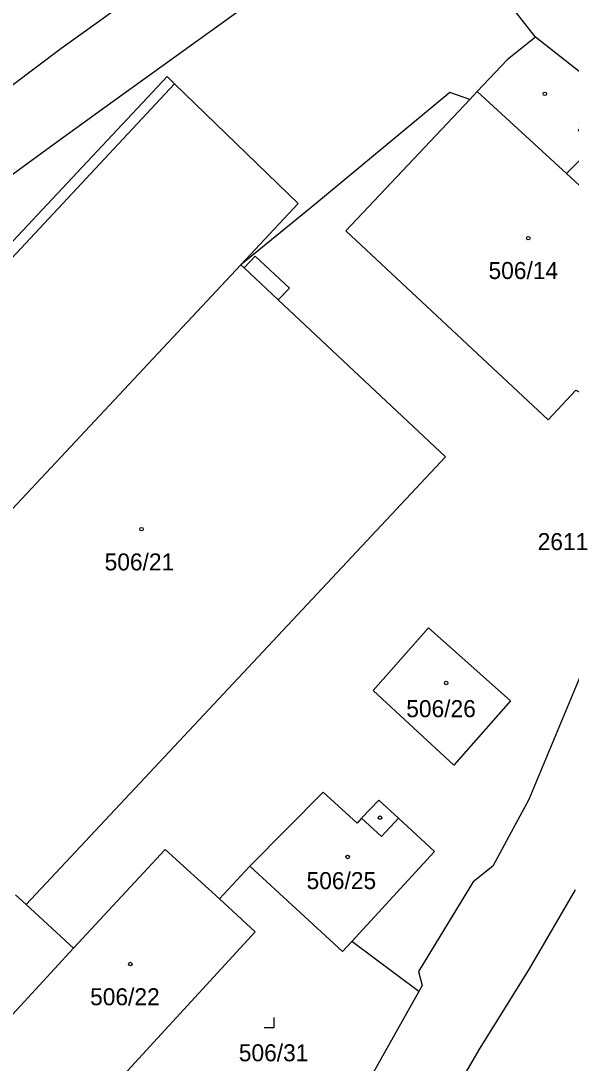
# Model space of a CAD drawing. Extents: x -679220 to -673243, y -1075091 to -1066557.
# Drawn here: x -677079.2 to -677024.2, y -1070793.9 to -1070689.7 of the extents above; entities that cross this region are included whole.
import ezdxf

# ---------------------------------------------------------------- set-up
doc = ezdxf.new("R2010")
doc.units = 0
for name, color, linetype in [('Hranice parcel', 7, 'Continuous'), ('Parcelní čísla', 7, 'Continuous'), ('Vnitřní kresba', 7, 'Continuous'), ('Značky budov', 7, 'Continuous'), ('Značky kultur', 7, 'Continuous')]:
    doc.layers.add(name, color=color, linetype=linetype)

msp = doc.modelspace()

# ---------------------------------------------------------------- linework, layer by layer
at = {"layer": 'Hranice parcel'}
for p, q in [((-677020.51, -1070697.05), (-677027.74, -1070691.36)), ((-677099.09, -1070758.91), (-677057.18, -1070714.13)), ((-677056.28, -1070774.23), (-677059.31, -1070777.52)), ((-677078.63, -1070778.07), (-677079.67, -1070777.1)), ((-677078.63, -1070778.07), (-677073.89, -1070782.45)), ((-677039.39, -1070786.77), (-677046.09, -1070781.76)), ((-677083.16, -1070792.51), (-677073.89, -1070782.45))]:
    msp.add_line(p, q, dxfattribs=at)
for points in [[(-677135.39, -1070729.77), (-677126.91, -1070726.13), (-677119.11, -1070722.08), (-677111.25, -1070717.42), (-677103.91, -1070713.3), (-677097.19, -1070709.11), (-677075.17, -1070692.52), (-677062.55, -1070683.44), (-677056.34, -1070679.02), (-677044.15, -1070670.16), (-677029.88, -1070660.86), (-677019.47, -1070653.76)], [(-677003.15, -1070655.19), (-677007.73, -1070657.23), (-677013.21, -1070659.83), (-677015.86, -1070661.26), (-677019.09, -1070662.86), (-677021.15, -1070664.15), (-677023.81, -1070665.65), (-677026.34, -1070667.21), (-677028.95, -1070668.79), (-677031.47, -1070670.4), (-677034.01, -1070671.98), (-677036.54, -1070673.73), (-677039.05, -1070675.44), (-677041.45, -1070677.28), (-677070.75, -1070698.39), (-677076.54, -1070702.6), (-677081.33, -1070706.06), (-677093, -1070715.15), (-677095.02, -1070716.41)], [(-677027.74, -1070691.36), (-677030.83, -1070687.38), (-676997.65, -1070663.02)], [(-677027.74, -1070691.36), (-677030.57, -1070693.65), (-677033.54, -1070696.8), (-677034.28, -1070697.59)], [(-677090.97, -1070723.48), (-677064.53, -1070695.31), (-677063.8, -1070696.05), (-677051.44, -1070708.01), (-677057.18, -1070714.13)], [(-677034.28, -1070697.59), (-677036.28, -1070696.89), (-677049.79, -1070708.11), (-677057.18, -1070714.13)], [(-677034.28, -1070697.59), (-677046.67, -1070710.74), (-677026.45, -1070729.62), (-677023.7, -1070726.67), (-677004.38, -1070736.72), (-676997.98, -1070729.55), (-677000.66, -1070726.99), (-676998.67, -1070724.91), (-677001.07, -1070722.57), (-677003.08, -1070724.67), (-677012.86, -1070715.31), (-677017.01, -1070711.34), (-677014.07, -1070708.12), (-677018.61, -1070704), (-677021.65, -1070707.35), (-677022.05, -1070707.36), (-677024.63, -1070704.99), (-677021.89, -1070702.22), (-677023.46, -1070700.67), (-677023.03, -1070700.24), (-677023.35, -1070699.92), (-677020.51, -1070697.05)], [(-677057.18, -1070714.13), (-677056.85, -1070714.44), (-677055.74, -1070713.25), (-677052.31, -1070716.45), (-677053.44, -1070717.64), (-677036.73, -1070733.34), (-677078.63, -1070778.07)], [(-676997.4, -1070741.72), (-677000.36, -1070741.19), (-677006.47, -1070740.6), (-677010.11, -1070741.84), (-677014, -1070744.73), (-677018.32, -1070748.82), (-677023.06, -1070754.8), (-677028.38, -1070767.57), (-677031.98, -1070774.25), (-677033.96, -1070775.82), (-677039.43, -1070784.79), (-677039.06, -1070786.18), (-677039.39, -1070786.77)], [(-677035.88, -1070764.16), (-677043.95, -1070756.69), (-677038.43, -1070750.41), (-677030.21, -1070757.73), (-677035.88, -1070764.16)], [(-677046.09, -1070781.76), (-677037.83, -1070772.79), (-677041.43, -1070769.44), (-677043.39, -1070767.65), (-677045.12, -1070769.46), (-677045.54, -1070769.95), (-677048.94, -1070766.86), (-677056.28, -1070774.23)], [(-677073.89, -1070782.45), (-677064.72, -1070772.58), (-677059.31, -1070777.52)], [(-677056.28, -1070774.23), (-677047.01, -1070782.76), (-677046.09, -1070781.76)], [(-677048.97, -1070841.27), (-677046.53, -1070827.88), (-677044.52, -1070822.41), (-677043.55, -1070818.31), (-677041.55, -1070813.73), (-677038.68, -1070806.91), (-677037.55, -1070802.28), (-677036.01, -1070797.18), (-677033.25, -1070792.43), (-677028.32, -1070784.52), (-677023.72, -1070776.62)], [(-677059.31, -1070777.52), (-677055.75, -1070780.81), (-677074.12, -1070800.85), (-677076.57, -1070798.6), (-677077.52, -1070799.64), (-677081.23, -1070796.22), (-677080.27, -1070795.18), (-677083.16, -1070792.51)], [(-677039.39, -1070786.77), (-677045.73, -1070798.1), (-677047.04, -1070802.64), (-677049.19, -1070809.83), (-677050.66, -1070814.68), (-677052.34, -1070818.42), (-677054.53, -1070823.8), (-677056.21, -1070827.09), (-677058.65, -1070832.51), (-677061.33, -1070834.18), (-677058.79, -1070838.11)]]:
    msp.add_lwpolyline(points, dxfattribs=at)
at = {"layer": 'Vnitřní kresba'}
for p, q in [((-677063.8, -1070696.05), (-677119.59, -1070755.82)), ((-677033.54, -1070696.8), (-677024.63, -1070704.99)), ((-677056.85, -1070714.44), (-677053.44, -1070717.64)), ((-677045.12, -1070769.46), (-677043.12, -1070771.28)), ((-677043.12, -1070771.28), (-677041.43, -1070769.44))]:
    msp.add_line(p, q, dxfattribs=at)
at = {"layer": 'Značky budov'}
for centre in [(-677026.8, -1070697.04), (-677028.45, -1070711.47), (-677067.1, -1070740.56), (-677036.65, -1070755.94), (-677043.26, -1070769.4), (-677046.5, -1070773.32), (-677068.21, -1070784.03)]:
    msp.add_circle(centre, 0.175, dxfattribs=at)
at = {"layer": 'Značky kultur'}
for p, q in [((-677053.83, -1070790.37), (-677053.83, -1070789.37)), ((-677054.83, -1070790.37), (-677053.83, -1070790.37))]:
    msp.add_line(p, q, dxfattribs=at)

# ---------------------------------------------------------------- texts
at = {"layer": 'Parcelní čísla'}
for s, p in [('506/14', (-677032.42, -1070715.55)), ('2611', (-677027.51, -1070742.65)), ('506/21', (-677070.78, -1070744.68)), ('506/26', (-677040.64, -1070759.35)), ('506/25', (-677050.6, -1070776.54)), ('506/22', (-677072.23, -1070788.15)), ('506/31', (-677057.37, -1070793.75))]:
    msp.add_text(s, height=1.7, dxfattribs=at).set_placement(p)

doc.saveas('drawing.dxf')
